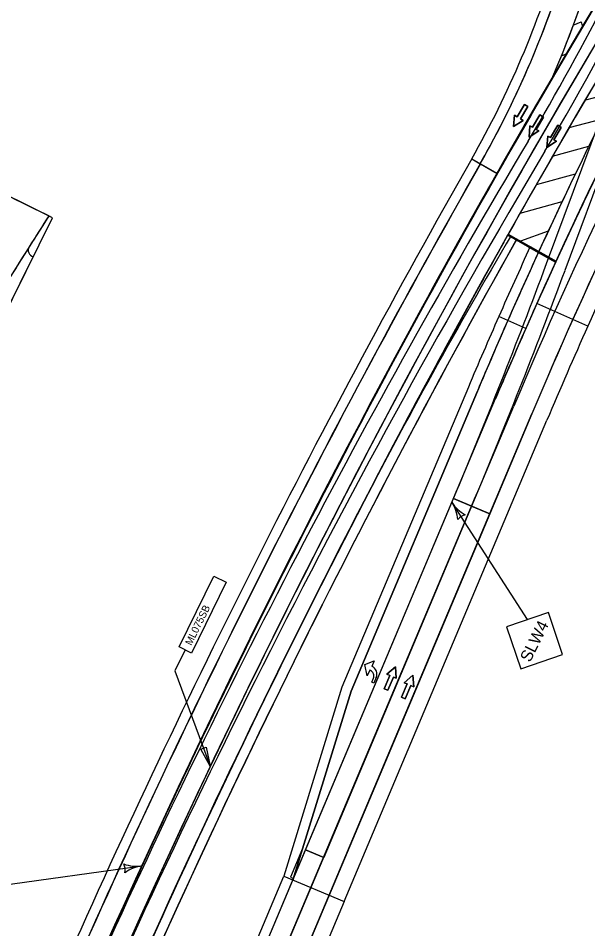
# Model space of a CAD drawing. Extents: x 14097936 to 14128734, y 8632000 to 8683104.
# Drawn here: x 14118650 to 14118997, y 8668139 to 8668694 of the extents above; entities that cross this region are included whole.
import ezdxf

# ---------------------------------------------------------------- set-up
doc = ezdxf.new("R2010")
doc.units = 0
for name, color, linetype in [('Cell', 7, 'Continuous'), ('dsn_stg_shd_prev', 7, 'Continuous'), ('dsnPaintExistingChannelizingLaneWhite', 7, 'Continuous'), ('dsnPaintExistingDottedLineWhite', 7, 'Continuous'), ('dsnPaintExistingEdgeLineLeftYellow', 7, 'Continuous'), ('dsnPaintExistingEdgeLineRightWhite', 7, 'Continuous'), ('dsnPaintExistingLaneLineWhite', 7, 'Continuous'), ('dsnPaintPlaceBrokenLaneWhite', 7, 'Continuous'), ('dsnPaintPlaceChannelizingLaneWhite', 7, 'Continuous'), ('dsnPaintPlaceChannelizingLaneYellow', 7, 'Continuous'), ('dsnPaintPlaceDottedLineWhite', 7, 'Continuous'), ('dsnPaintPlaceEdgeLineLeftYellow', 7, 'Continuous'), ('dsnPaintPlaceEdgeLineRightWhite', 7, 'Continuous'), ('dsnPaintPlaceLaneLineWhite', 7, 'Continuous'), ('dsnPaintRemoveEdgeLineLeftYellow', 7, 'Continuous'), ('dsnPaintRemoveEdgeLineRightWhite', 7, 'Continuous'), ('dsnShadingPaved', 7, 'Continuous'), ('dsnStdLabel', 7, 'Continuous'), ('dsnStgShadingPrevPav', 7, 'Continuous'), ('dsnStgShadingPropPav', 7, 'Continuous'), ('dsnTapeRemoveChannelizingLaneWhite', 7, 'Continuous'), ('dsnTapeRemoveChannelizingLaneYellow', 7, 'Continuous'), ('dsnTapeRemoveEdgeLaneWhite', 7, 'Continuous'), ('dsnTapeRemoveEdgeLaneYellow', 7, 'Continuous'), ('Level 2', 7, 'Continuous'), ('Level 5', 7, 'Continuous'), ('Text', 7, 'Continuous')]:
    doc.layers.add(name, color=color, linetype=linetype)

msp = doc.modelspace()

# ---------------------------------------------------------------- linework, layer by layer
at = {"layer": 'Cell'}
for p, q in [((14118865.16, 8668298.96), (14118865.33, 8668298.89)), ((14118864.33, 8668296.46), (14118864.04, 8668296.58))]:
    msp.add_line(p, q, dxfattribs=at)
for points in [[(14118860.99, 8668300.1), (14118866.73, 8668302.29), (14118865.16, 8668298.96)], [(14118860.99, 8668300.1), (14118866.73, 8668302.29), (14118865.16, 8668298.96)], [(14118864.04, 8668296.58), (14118862.48, 8668293.24), (14118860.99, 8668300.1)], [(14118864.04, 8668296.58), (14118862.48, 8668293.24), (14118860.99, 8668300.1)], [(14118865.16, 8668298.96), (14118865.33, 8668298.89)], [(14118864.33, 8668296.46), (14118864.04, 8668296.58)], [(14118867.94, 8668292.13), (14118866.55, 8668288.73), (14118865.17, 8668289.3), (14118866.16, 8668291.73)], [(14118867.94, 8668292.13), (14118866.55, 8668288.73), (14118865.17, 8668289.3), (14118866.16, 8668291.73)]]:
    msp.add_lwpolyline(points, dxfattribs=at)
for centre, major_axis in [((14118863.34, 8668294.02), (-2, -4.86)), ((14118863.34, 8668294.02), (-2, -4.86)), ((14118862.94, 8668293.05), (-1.4, -3.4)), ((14118862.94, 8668293.05), (-1.4, -3.4))]:
    msp.add_ellipse(centre, major_axis=major_axis, ratio=0.9474, start_param=1.570796, end_param=3.141593, dxfattribs=at)
at = {"layer": 'dsn_stg_shd_prev'}
for p, q in [((14118926.13, 8668608.49), (14118941.74, 8668599.61)), ((14118926.13, 8668608.49), (14118941.74, 8668599.61)), ((14118948.03, 8668561.98), (14118953.3, 8668559.01)), ((14118966.72, 8668551.47), (14118977.22, 8668545.57))]:
    msp.add_line(p, q, dxfattribs=at)
for points in [[(14118398.34, 8668220.99), (14118477.41, 8668181.9), (14118670.56, 8668572.56), (14118624.96, 8668595.1)], [(14118948.03, 8668561.98), (14118953.26, 8668559.03), (14118966.72, 8668551.47)]]:
    msp.add_lwpolyline(points, dxfattribs=at)
for centre, radius, start, end in [((14123732.59, 8665873.82), 5512, 146.41866, 157.1633), ((14123732.59, 8665873.82), 5512, 146.50213, 150.36196), ((14121591.75, 8667345.11), 2876.96, 147.23629, 155.33788), ((14118409.81, 8668902.17), 594, 330.3689, 343.63038), ((14123732.96, 8665874.38), 5530, 150.3689, 156.09911), ((14123732.59, 8665873.82), 5512, 150.36196, 157.1633), ((14123733.72, 8665873.34), 5489.23, 150.6724, 157.1633), ((14123733.72, 8665873.34), 5489.23, 150.6724, 157.1633), ((14123732.96, 8665874.38), 5482, 150.67799, 157.1633)]:
    msp.add_arc(centre, radius, start, end, dxfattribs=at)
at = {"layer": 'dsnPaintExistingChannelizingLaneWhite'}
msp.add_arc((14118409.81, 8668902.17), 616, 336.56541, 343.63038, dxfattribs=at)
at = {"layer": 'dsnPaintExistingDottedLineWhite'}
msp.add_arc((14123732.96, 8665874.38), 5512, 152.23375, 154.51073, dxfattribs=at)
at = {"layer": 'dsnPaintExistingEdgeLineLeftYellow'}
msp.add_line((14118759.37, 8668031.7), (14118817.06, 8668168.68), dxfattribs=at)
msp.add_arc((14123732.96, 8665874.38), 5488, 152.69211, 157.1633, dxfattribs=at)
at = {"layer": 'dsnPaintExistingEdgeLineRightWhite'}
msp.add_line((14110924.38, 8649364.51), (14118874.68, 8668243.67), dxfattribs=at)
for centre, radius, start, end in [((14118409.81, 8668902.17), 600, 334.79009, 343.63038), ((14118421.29, 8668896.21), 587.08, 330.32024, 334.83876), ((14123732.96, 8665874.38), 5524, 150.3689, 156.09858)]:
    msp.add_arc(centre, radius, start, end, dxfattribs=at)
at = {"layer": 'dsnPaintExistingLaneLineWhite'}
msp.add_arc((14122745.39, 8666422.79), 4382.73, 149.34837, 152.56312, dxfattribs=at)
at = {"layer": 'dsnPaintPlaceBrokenLaneWhite'}
msp.add_line((14118537.63, 8667474.22), (14118951.74, 8668457.58), dxfattribs=at)
for centre, radius, start in [((14123732.96, 8665874.38), 5500, 147.11705), ((14121592.11, 8667345.68), 2864.95, 151.16499)]:
    msp.add_arc(centre, radius, start, 157.1633, dxfattribs=at)
at = {"layer": 'dsnPaintPlaceChannelizingLaneWhite'}
for p, q in [((14118988.09, 8668689.91), (14118992.79, 8668692.09)), ((14118980.89, 8668671.25), (14118983.27, 8668672.26))]:
    msp.add_line(p, q, dxfattribs=at)
for centre, radius, start, end in [((14123732.96, 8665874.38), 5512, 148.26304, 149.67774), ((14124357.11, 8670043.79), 5532, 194.14298, 194.17822), ((14124346.93, 8670026.57), 5532, 194.17092, 194.17822)]:
    msp.add_arc(centre, radius, start, end, dxfattribs=at)
at = {"layer": 'dsnPaintPlaceChannelizingLaneYellow'}
for p, q in [((14118995.73, 8668644.44), (14119013.98, 8668649.22)), ((14118985.49, 8668627.51), (14119005.79, 8668632.9)), ((14118975.49, 8668610.19), (14118997.51, 8668616.13)), ((14118965.55, 8668592.83), (14118989.36, 8668599.35)), ((14118955.67, 8668575.44), (14118981.34, 8668582.57)), ((14118669.08, 8668573.29), (14118667.77, 8668572.94)), ((14118948.4, 8668562.54), (14118967.09, 8668552.03)), ((14118972.84, 8668564.47), (14118955.94, 8668558.3))]:
    msp.add_line(p, q, dxfattribs=at)
for centre, radius, start, end in [((14123748.96, 8665864.73), 5506.68, 148.38653, 150.66501), ((14121592.11, 8667345.68), 2888.95, 150.97391, 155.3184), ((14127939.53, 8662698.67), 10976, 147.638369, 147.75486), ((14118659.71, 8668552.7), 4, 147.7549, 256.9938)]:
    msp.add_arc(centre, radius, start, end, dxfattribs=at)
at = {"layer": 'dsnPaintPlaceDottedLineWhite'}
msp.add_arc((14123732.96, 8665874.38), 5512, 154.51073, 156.09858, dxfattribs=at)
at = {"layer": 'dsnPaintPlaceEdgeLineLeftYellow'}
for p, q in [((14118852.57, 8668283.93), (14118929.62, 8668466.89)), ((14118817.06, 8668168.68), (14118852.57, 8668283.93))]:
    msp.add_line(p, q, dxfattribs=at)
for centre, radius, start, end in [((14123735.81, 8665873.06), 5491.14, 150.67353, 157.16217), ((14121592.11, 8667345.68), 2888.95, 155.3184, 156.23389), ((14121619.49, 8667333.88), 2918.75, 156.23864, 157.15856)]:
    msp.add_arc(centre, radius, start, end, dxfattribs=at)
at = {"layer": 'dsnPaintPlaceEdgeLineRightWhite'}
msp.add_line((14118874.68, 8668243.67), (14118962.79, 8668452.92), dxfattribs=at)
msp.add_arc((14121592.11, 8667345.68), 2852.95, 151.16499, 157.1633, dxfattribs=at)
at = {"layer": 'dsnPaintPlaceLaneLineWhite'}
msp.add_line((14118863.63, 8668279.27), (14118940.68, 8668462.24), dxfattribs=at)
for centre, radius, start, end in [((14121592.11, 8667345.68), 2876.95, 150.94619, 156.23387), ((14121619.49, 8667333.88), 2906.75, 156.23864, 157.15856)]:
    msp.add_arc(centre, radius, start, end, dxfattribs=at)
at = {"layer": 'dsnPaintRemoveEdgeLineLeftYellow'}
msp.add_line((14118817.06, 8668168.68), (14118914.86, 8668400.93), dxfattribs=at)
msp.add_arc((14121955.85, 8666791.92), 3488, 149.50762, 152.69211, dxfattribs=at)
at = {"layer": 'dsnPaintRemoveEdgeLineRightWhite'}
msp.add_lwpolyline([(14118693.19, 8667843.63), (14118809.62, 8668120.12), (14118926.06, 8668396.6)], dxfattribs=at)
msp.add_lwpolyline([(14118693.19, 8667843.63), (14118809.62, 8668120.12), (14118926.06, 8668396.6)], dxfattribs=at)
at = {"layer": 'dsnShadingPaved'}
for p, q in [((14118931.35, 8668605.52), (14118941.5, 8668599.74)), ((14118668.25, 8668573.7), (14118646.62, 8668584.4)), ((14118915, 8668401.26), (14118940.68, 8668462.24)), ((14118915, 8668401.26), (14118940.68, 8668462.24)), ((14118962.79, 8668452.92), (14118937.12, 8668391.94)), ((14118824.82, 8668187.11), (14118915, 8668401.26)), ((14118937.12, 8668391.94), (14118915, 8668401.26)), ((14118835.88, 8668182.45), (14118926.06, 8668396.6)), ((14118926.06, 8668396.6), (14118937.12, 8668391.94)), ((14118937.12, 8668391.94), (14118374.42, 8667055.73)), ((14118352.3, 8667065.05), (14118824.82, 8668187.11)), ((14118817.06, 8668168.68), (14118824.82, 8668187.11)), ((14118824.82, 8668187.11), (14118835.88, 8668182.45))]:
    msp.add_line(p, q, dxfattribs=at)
for points in [[(14118470.24, 8668185.44), (14118477.41, 8668181.9), (14118658.81, 8668548.81)], [(14118948.15, 8668509.94), (14118947.75, 8668509.02), (14118946.13, 8668505.32), (14118944.11, 8668500.7), (14118942.09, 8668496.08), (14118940.09, 8668491.45), (14118938.22, 8668487.1), (14118938.1, 8668486.82), (14118936.11, 8668482.19), (14118934.13, 8668477.55), (14118932.16, 8668472.91), (14118930.19, 8668468.26), (14118929.62, 8668466.89), (14118852.57, 8668283.93), (14118817.06, 8668168.68)]]:
    msp.add_lwpolyline(points, dxfattribs=at)
msp.add_lwpolyline([(14118824.82, 8668187.11), (14118915, 8668401.26), (14118926.06, 8668396.6), (14118835.88, 8668182.45)], close=True, dxfattribs=at)
for centre, radius, start, end in [((14123732.96, 8665874.38), 5500, 145.2497, 157.1633), ((14123732.96, 8665874.38), 5488, 145.2497, 157.1633), ((14123732.96, 8665874.38), 5500, 146.42378, 157.1633), ((14121592.11, 8667345.68), 2876.95, 147.15737, 157.1633), ((14121592.11, 8667345.68), 2852.95, 147.15737, 157.1633), ((14123655.03, 8665915.77), 5424.12, 146.80648, 157.24675), ((14121592.11, 8667345.68), 2876.95, 149.16283, 157.1633), ((14121592.11, 8667345.68), 2888.95, 150.97391, 156.23389), ((14118409.81, 8668902.17), 600, 330.3689, 343.63038), ((14118409.81, 8668902.17), 616, 336.78135, 343.63038), ((14123655.03, 8665915.77), 5424.12, 149.6152, 150.342), ((14123732.96, 8665874.38), 5524, 150.3689, 156.09858), ((14123732.96, 8665874.38), 5512, 150.3689, 157.1633), ((14127939.53, 8662698.67), 10976, 147.638369, 149.921821), ((14127939.53, 8662698.67), 10976, 147.75486, 148.384714), ((14118659.71, 8668552.7), 4, 147.7549, 256.9938)]:
    msp.add_arc(centre, radius, start, end, dxfattribs=at)
at = {"layer": 'dsnStdLabel'}
for p, q in [((14118960.12, 8668327.46), (14118914.06, 8668399.03)), ((14118637.23, 8668165.11), (14118725.07, 8668177.26))]:
    msp.add_line(p, q, dxfattribs=at)
for points in [[(14118477.41, 8668181.9), (14118670.56, 8668572.56), (14118446.45, 8668683.36), (14118253.3, 8668292.7)], [(14118955.99, 8668297.56), (14118981.56, 8668306.21), (14118972.91, 8668331.79), (14118947.33, 8668323.14)]]:
    msp.add_lwpolyline(points, close=True, dxfattribs=at)
for centre, radius, start, end in [((14118894.76, 8668386.6), 22.95, 4.6978, 32.7691), ((14118933.35, 8668411.45), 22.95, 212.7689, 240.8402), ((14118924.47, 8668382.85), 8.86, 105.0348, 140.5032), ((14118721.93, 8668199.99), 22.95, 249.7998, 277.8711), ((14118706.01, 8668174.62), 8.86, 350.1368, 25.6052), ((14118728.22, 8668154.52), 22.95, 97.8709, 125.9422)]:
    msp.add_arc(centre, radius, start, end, dxfattribs=at)
at = {"layer": 'dsnStgShadingPrevPav'}
for p, q in [((14118926.13, 8668608.49), (14118931.35, 8668605.52)), ((14118926.25, 8668608.44), (14118941.85, 8668599.56)), ((14118948.4, 8668562.54), (14118953.63, 8668559.6)), ((14118961.85, 8668554.98), (14118977.59, 8668546.13)), ((14118967.09, 8668552.03), (14118977.59, 8668546.13)), ((14118996.9, 8668506.38), (14118965.9, 8668520.25)), ((14118959.14, 8668505.1), (14118942.66, 8668512.36)), ((14118924.09, 8668469.22), (14118847.04, 8668286.26)), ((14118848.39, 8668155.49), (14118972.01, 8668449.04)), ((14118847.04, 8668286.26), (14118811.53, 8668171.01)), ((14115895.65, 8661246.83), (14118811.53, 8668171.01)), ((14118811.53, 8668171.01), (14118848.39, 8668155.49)), ((14118811.53, 8668171.01), (14118848.39, 8668155.49)), ((14118848.39, 8668155.49), (14115932.51, 8661231.3))]:
    msp.add_line(p, q, dxfattribs=at)
for points in [[(14118398.42, 8668220.96), (14118477.41, 8668181.9), (14118670.56, 8668572.56), (14118624.99, 8668595.09)], [(14118948.4, 8668562.54), (14118953.63, 8668559.59), (14118967.09, 8668552.03)], [(14118965.9, 8668520.25), (14118959.14, 8668505.1), (14118942.66, 8668512.35)]]:
    msp.add_lwpolyline(points, dxfattribs=at)
for centre, radius, start, end in [((14123732.96, 8665874.38), 5512, 146.41866, 157.1633), ((14121592.12, 8667345.67), 2876.96, 147.23629, 155.33788), ((14123732.96, 8665874.38), 5530, 150.3689, 156.09911), ((14123732.96, 8665874.38), 5524, 150.3689, 156.09858), ((14123733.07, 8665874.33), 5524, 150.3689, 156.09858), ((14123732.7, 8665873.77), 5512, 150.36196, 157.1633), ((14123734.09, 8665873.9), 5489.23, 150.6724, 157.1633), ((14123732.96, 8665874.38), 5482, 150.67101, 157.1633), ((14123732.96, 8665874.38), 5488, 150.67095, 151.14296), ((14121630.39, 8667328.45), 2936.92, 155.31533, 156.22718), ((14121631.5, 8667327.96), 2920.14, 155.34458, 156.22722), ((14123732.96, 8665874.38), 5488, 151.14296, 157.1633), ((14121592.11, 8667345.68), 2894.95, 156.23384, 157.1633), ((14121592.11, 8667345.68), 2842.95, 155.90343, 157.1633)]:
    msp.add_arc(centre, radius, start, end, dxfattribs=at)
at = {"layer": 'dsnStgShadingPropPav'}
for p, q in [((14118926.13, 8668608.49), (14118941.74, 8668599.61)), ((14118996.9, 8668506.38), (14118965.87, 8668520.26)), ((14118959.14, 8668505.1), (14118948.15, 8668509.94)), ((14118929.62, 8668466.89), (14118852.57, 8668283.93)), ((14118863.63, 8668279.27), (14118940.68, 8668462.24)), ((14118852.57, 8668283.93), (14118822.97, 8668187.89)), ((14118817.44, 8668169.6), (14118863.63, 8668279.27)), ((14118822.97, 8668187.89), (14118815.6, 8668170.38)), ((14118815.6, 8668170.38), (14118817.44, 8668169.6))]:
    msp.add_line(p, q, dxfattribs=at)
for centre, radius, start, end in [((14123732.59, 8665873.82), 5512, 146.50213, 150.36196), ((14118409.81, 8668902.17), 594, 330.3689, 343.63038), ((14121592.11, 8667345.68), 2876.95, 152.63404, 155.90343), ((14121592.11, 8667345.68), 2842.95, 152.63404, 155.90343), ((14121592.11, 8667345.68), 2888.95, 156.23384, 157.1633), ((14121592.11, 8667345.68), 2876.95, 156.23384, 157.1633)]:
    msp.add_arc(centre, radius, start, end, dxfattribs=at)
at = {"layer": 'dsnTapeRemoveChannelizingLaneWhite'}
msp.add_line((14118983.04, 8668540.5), (14119108.11, 8668877.26), dxfattribs=at)
for centre, radius, start, end in [((14117682.33, 8669381.12), 1488, 329.20119, 337.13903), ((14115608.24, 8669793.78), 3600, 337.1633, 339.62671)]:
    msp.add_arc(centre, radius, start, end, dxfattribs=at)
at = {"layer": 'dsnTapeRemoveChannelizingLaneYellow'}
msp.add_line((14118971.78, 8668544.68), (14119088.49, 8668858.92), dxfattribs=at)
for centre, radius, start, end in [((14117682.32, 8669381.12), 1500, 329.20119, 339.62671), ((14115600.44, 8669796.87), 3596.39, 337.16043, 339.62383)]:
    msp.add_arc(centre, radius, start, end, dxfattribs=at)
at = {"layer": 'dsnTapeRemoveEdgeLaneWhite'}
msp.add_arc((14123265.63, 8666052.94), 5012, 149.20104, 155.80033, dxfattribs=at)
msp.add_arc((14123265.63, 8666052.94), 5012, 149.20104, 155.80033, dxfattribs=at)
at = {"layer": 'dsnTapeRemoveEdgeLaneYellow'}
for start, end in [(149.20107, 153.18219), (153.18219, 156.97073)]:
    msp.add_arc((14123265.63, 8666052.94), 5000, start, end, dxfattribs=at)
at = {"layer": 'Level 2'}
for points in [[(14118960.4, 8668640.37), (14118958.25, 8668641.66), (14118953.77, 8668634.14), (14118952.16, 8668635.1), (14118951.64, 8668628.14), (14118957.52, 8668631.9), (14118955.91, 8668632.86)], [(14118969.91, 8668633.96), (14118967.76, 8668635.25), (14118963.28, 8668627.73), (14118961.67, 8668628.69), (14118961.15, 8668621.72), (14118967.04, 8668625.49), (14118965.43, 8668626.45)], [(14118980.7, 8668627.64), (14118978.55, 8668628.93), (14118974.07, 8668621.41), (14118972.46, 8668622.37), (14118971.94, 8668615.41), (14118977.82, 8668619.17), (14118976.21, 8668620.13)], [(14118872.71, 8668285.37), (14118875.02, 8668284.39), (14118878.43, 8668292.45), (14118880.15, 8668291.72), (14118879.71, 8668298.69), (14118874.4, 8668294.16), (14118876.12, 8668293.43)], [(14118883.31, 8668280.24), (14118885.61, 8668279.26), (14118889.02, 8668287.32), (14118890.75, 8668286.59), (14118890.31, 8668293.56), (14118884.99, 8668289.03), (14118886.72, 8668288.29)]]:
    msp.add_lwpolyline(points, close=True, dxfattribs=at)
at = {"layer": 'Level 5'}
for points in [[(14118955.91, 8668632.86), (14118957.52, 8668631.9), (14118951.64, 8668628.14), (14118952.16, 8668635.1), (14118953.77, 8668634.14), (14118958.25, 8668641.66), (14118960.4, 8668640.37), (14118955.91, 8668632.86)], [(14118965.43, 8668626.45), (14118967.04, 8668625.49), (14118961.15, 8668621.72), (14118961.67, 8668628.69), (14118963.28, 8668627.73), (14118967.76, 8668635.25), (14118969.91, 8668633.96), (14118965.43, 8668626.45)], [(14118976.21, 8668620.13), (14118977.82, 8668619.17), (14118971.94, 8668615.41), (14118972.46, 8668622.37), (14118974.07, 8668621.41), (14118978.55, 8668628.93), (14118980.7, 8668627.64), (14118976.21, 8668620.13)], [(14118876.12, 8668293.43), (14118874.4, 8668294.16), (14118879.71, 8668298.69), (14118880.15, 8668291.72), (14118878.43, 8668292.45), (14118875.02, 8668284.39), (14118872.71, 8668285.37), (14118876.12, 8668293.43)], [(14118886.72, 8668288.29), (14118884.99, 8668289.03), (14118890.31, 8668293.56), (14118890.75, 8668286.59), (14118889.02, 8668287.32), (14118885.61, 8668279.26), (14118883.31, 8668280.24), (14118886.72, 8668288.29)]]:
    msp.add_lwpolyline(points, dxfattribs=at)
at = {"layer": 'Text'}
for points in [[(14118747.67, 8668310.84), (14118768.93, 8668353.99), (14118776.46, 8668350.28), (14118755.21, 8668307.12)], [(14118747.67, 8668310.84), (14118768.93, 8668353.99), (14118776.46, 8668350.28), (14118755.21, 8668307.12)], [(14118766.75, 8668238.02), (14118760.96, 8668248.46), (14118764.28, 8668249.7)]]:
    msp.add_lwpolyline(points, close=True, dxfattribs=at)
msp.add_lwpolyline([(14118751.44, 8668308.98), (14118745.04, 8668296.19), (14118766.75, 8668238.02)], dxfattribs=at)

# ---------------------------------------------------------------- texts
at = {"layer": 'dsnStdLabel'}
msp.add_text('SLW4', height=7.2, rotation=63.6912, dxfattribs=at).set_placement((14118961.71, 8668301.02))
at = {"layer": 'Text'}
msp.add_text('ML075SB', height=4.484, rotation=63.7805, dxfattribs=at).set_placement((14118755.18, 8668311.36))

doc.saveas('drawing.dxf')
